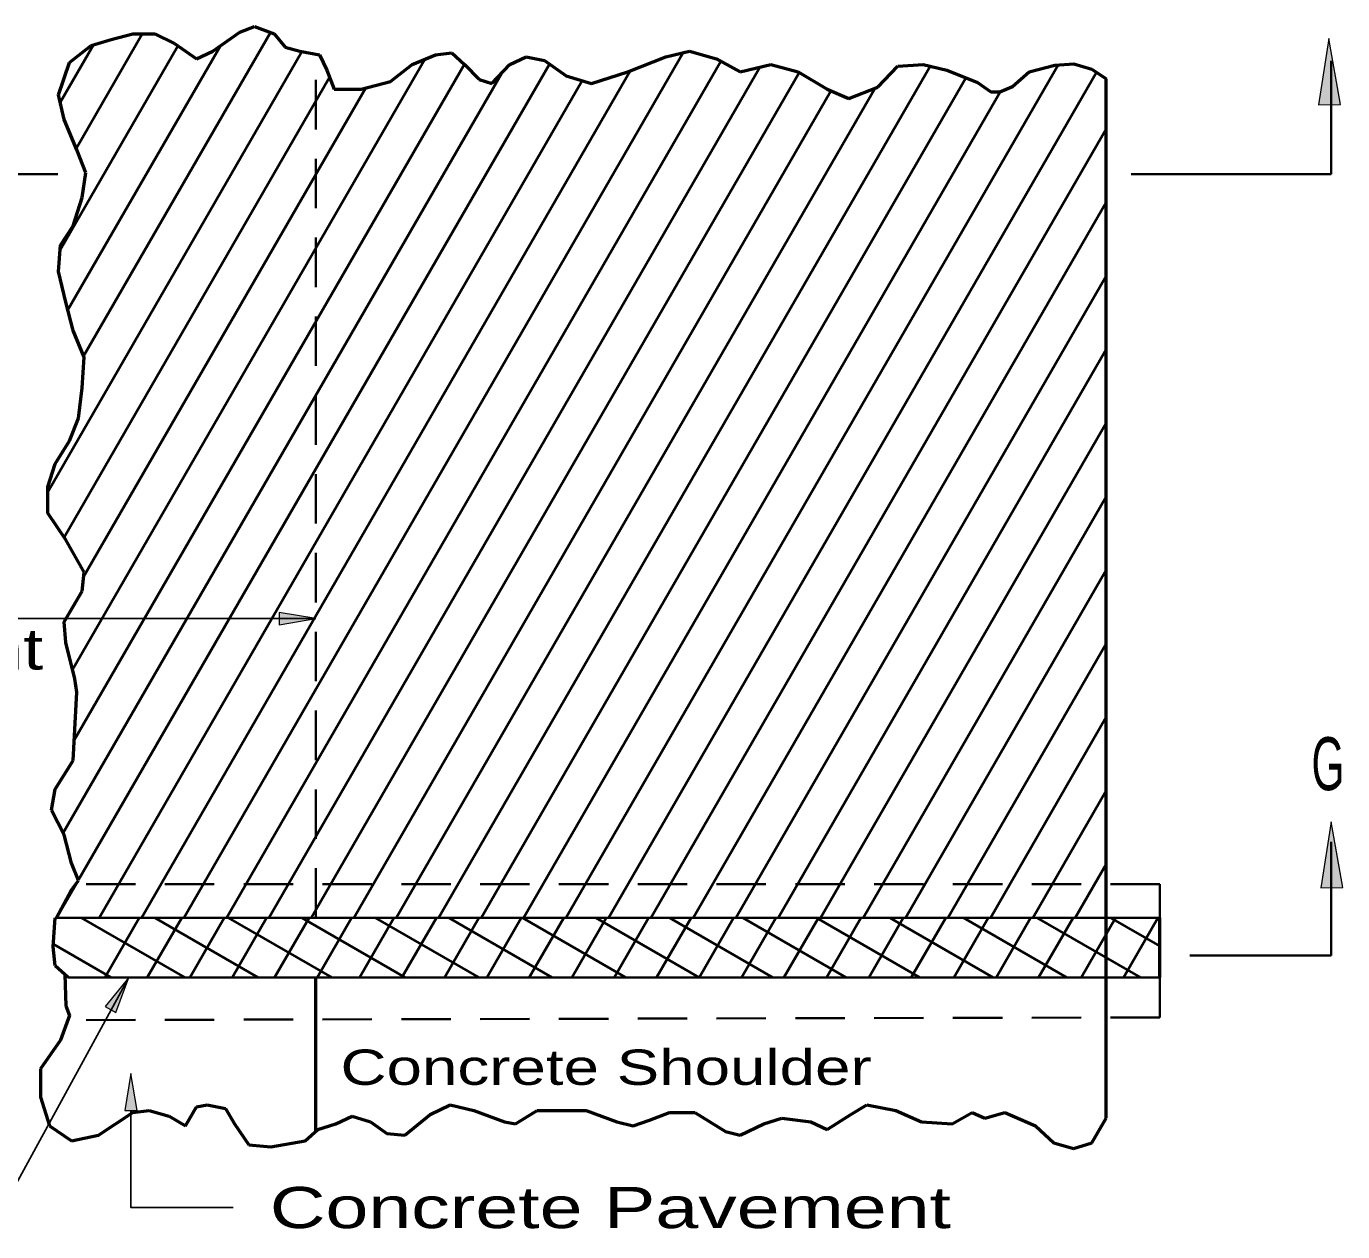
# Model space of a CAD drawing. Extents: x 14 to 49.3, y 28 to 50.
# Drawn here: x 25.568 to 30.044, y 32.796 to 36.894 of the extents above; entities that cross this region are included whole.
import ezdxf

# ---------------------------------------------------------------- set-up
doc = ezdxf.new("R2010")
doc.units = 0
doc.header["$LTSCALE"] = 0.056
doc.linetypes.add('MEDIUM_DASHED', pattern=[4.5, 3, -1.5])
for name, color, linetype, lineweight in [('1', 7, 'Continuous', 35), ('2', 7, 'MEDIUM_DASHED', 35), ('3', 7, 'Continuous', 13), ('5', 7, 'Continuous', 35)]:
    doc.layers.add(name, color=color, linetype=linetype, lineweight=lineweight)

msp = doc.modelspace()

# ---------------------------------------------------------------- hatches: boundary and pattern name
at = {"layer": '3'}
for points in [[(29.96183, 36.62733), (30.03667, 36.628), (29.99783, 36.852), (29.99783, 36.852)], [(29.96183, 36.62733), (30.03667, 36.628), (29.99783, 36.852), (29.99783, 36.852)], [(26.42775, 34.90125), (26.42775, 34.85958), (26.55275, 34.88042), (26.55275, 34.88042)], [(29.96967, 33.96517), (30.0445, 33.96583), (30.00567, 34.18983), (30.00567, 34.18983)], [(25.83633, 33.562), (25.87267, 33.54142), (25.91625, 33.66042), (25.91625, 33.66042)], [(25.90292, 33.20842), (25.94458, 33.20842), (25.92375, 33.33342), (25.92375, 33.33342)]]:
    msp.add_hatch(color=256, dxfattribs=at).paths.add_polyline_path(points)

# ---------------------------------------------------------------- linework, layer by layer
at = {"layer": '1', "lineweight": 53}
for p, q in [((26.29425, 36.87433), (26.3435, 36.89375)), ((26.3435, 36.89375), (26.41133, 36.86792)), ((25.78883, 36.82908), (25.85658, 36.8485)), ((25.85658, 36.8485), (25.93058, 36.86792)), ((25.93058, 36.86792), (26.0045, 36.86792)), ((26.0045, 36.86792), (26.07233, 36.83558)), ((26.20175, 36.80967), (26.29425, 36.87433)), ((26.41133, 36.86792), (26.44833, 36.82267)), ((25.71483, 36.77092), (25.78883, 36.82908)), ((26.07233, 36.83558), (26.14625, 36.78383)), ((26.14625, 36.78383), (26.20175, 36.80967)), ((26.44833, 36.82267), (26.49758, 36.80967)), ((26.49758, 36.80967), (26.56542, 36.79675)), ((26.95992, 36.79675), (27.01533, 36.80325)), ((27.01533, 36.80325), (27.0585, 36.76442)), ((27.74267, 36.79033), (27.82275, 36.80967)), ((27.82275, 36.80967), (27.91525, 36.78383)), ((25.67783, 36.661), (25.71483, 36.77092)), ((26.56542, 36.79675), (26.59008, 36.745)), ((26.80583, 36.70625), (26.87975, 36.76442)), ((26.87975, 36.76442), (26.95992, 36.79675)), ((27.0585, 36.76442), (27.10783, 36.71275)), ((27.15092, 36.69975), (27.21258, 36.76442)), ((27.21258, 36.76442), (27.26808, 36.79033)), ((27.26808, 36.79033), (27.32967, 36.77733)), ((27.32967, 36.77733), (27.40367, 36.72567)), ((27.61325, 36.73858), (27.74267, 36.79033)), ((27.91525, 36.78383), (27.99533, 36.73858)), ((27.99533, 36.73858), (28.10017, 36.76442)), ((28.10017, 36.76442), (28.19258, 36.73858)), ((28.46383, 36.68683), (28.53158, 36.758)), ((28.53158, 36.758), (28.61792, 36.76442)), ((28.61792, 36.76442), (28.698, 36.745)), ((28.97858, 36.73908), (29.0655, 36.76192)), ((29.0655, 36.76192), (29.13075, 36.7665)), ((29.13075, 36.7665), (29.19158, 36.74825)), ((26.59008, 36.745), (26.61475, 36.68042)), ((27.10783, 36.71275), (27.15092, 36.69975)), ((27.40367, 36.72567), (27.48992, 36.69975)), ((27.48992, 36.69975), (27.61325, 36.73858)), ((28.19258, 36.73858), (28.29125, 36.68042)), ((28.698, 36.745), (28.80283, 36.70275)), ((28.92208, 36.68892), (28.97858, 36.73908)), ((29.19158, 36.74825), (29.24042, 36.71558)), ((29.24042, 33.18192), (29.24042, 36.71558)), ((26.61475, 36.68042), (26.70717, 36.68042)), ((26.70717, 36.68042), (26.80583, 36.70625)), ((28.29125, 36.68042), (28.36517, 36.64808)), ((28.36517, 36.64808), (28.46383, 36.68683)), ((28.80283, 36.70275), (28.84817, 36.67067)), ((28.84817, 36.67067), (28.87858, 36.67067)), ((28.87858, 36.67067), (28.92208, 36.68892)), ((25.69633, 36.57692), (25.67783, 36.661)), ((25.7395, 36.47342), (25.69633, 36.57692)), ((25.77033, 36.39583), (25.7395, 36.47342)), ((25.758, 36.312), (25.77033, 36.39583)), ((25.72717, 36.215), (25.758, 36.312)), ((25.684, 36.15033), (25.72717, 36.215)), ((25.67783, 36.05975), (25.684, 36.15033)), ((25.7025, 35.95633), (25.67783, 36.05975)), ((25.72717, 35.85933), (25.7025, 35.95633)), ((25.76417, 35.76875), (25.72717, 35.85933)), ((25.758, 35.66525), (25.76417, 35.76875)), ((25.74567, 35.56183), (25.758, 35.66525)), ((25.71483, 35.48425), (25.74567, 35.56183)), ((25.6655, 35.40658), (25.71483, 35.48425)), ((25.64083, 35.32875), (25.6655, 35.40658)), ((25.64083, 35.23825), (25.64083, 35.32875)), ((25.7025, 35.14767), (25.64083, 35.23825)), ((25.76417, 35.03775), (25.7025, 35.14767)), ((25.758, 34.97308), (25.76417, 35.03775)), ((25.69633, 34.86967), (25.758, 34.97308)), ((25.7025, 34.7985), (25.69633, 34.86967)), ((25.73333, 34.67567), (25.7025, 34.7985)), ((25.7395, 34.63042), (25.73333, 34.67567)), ((25.72717, 34.39758), (25.7395, 34.63042)), ((25.6655, 34.30058), (25.72717, 34.39758)), ((25.65317, 34.2295), (25.6655, 34.30058)), ((25.69633, 34.14542), (25.65317, 34.2295)), ((25.721, 34.04842), (25.69633, 34.14542)), ((25.74567, 33.99017), (25.721, 34.04842)), ((25.721, 33.95783), (25.74567, 33.99017)), ((25.67017, 33.86342), (25.721, 33.95783)), ((25.65933, 33.76392), (25.66617, 33.86342)), ((29.42325, 33.66042), (29.42325, 33.86342)), ((25.6655, 33.69925), (25.65933, 33.76392)), ((25.71017, 33.66042), (25.6655, 33.69925)), ((25.69925, 33.66992), (25.7025, 33.56342)), ((26.55083, 33.66042), (26.55083, 33.13558)), ((25.71483, 33.53108), (25.684, 33.447)), ((25.7025, 33.56342), (25.71483, 33.53108)), ((25.684, 33.447), (25.61625, 33.35)), ((25.61625, 33.35), (25.61625, 33.253)), ((25.61625, 33.253), (25.647, 33.15608)), ((26.10933, 33.15608), (26.14625, 33.22067)), ((26.14625, 33.22067), (26.18325, 33.22717)), ((26.18325, 33.22717), (26.24492, 33.21425)), ((26.94142, 33.19483), (27.00917, 33.22717)), ((27.00917, 33.22717), (27.08933, 33.20775)), ((28.37133, 33.19483), (28.42683, 33.22717)), ((28.42683, 33.22717), (28.52542, 33.20775)), ((25.81342, 33.12375), (25.93058, 33.20133)), ((25.93058, 33.20133), (25.986, 33.20775)), ((25.986, 33.20775), (26.05383, 33.18833)), ((26.05383, 33.18833), (26.10933, 33.15608)), ((26.24492, 33.21425), (26.27575, 33.1625)), ((26.62092, 33.1625), (26.67633, 33.18833)), ((26.67633, 33.18833), (26.738, 33.169)), ((26.85508, 33.12375), (26.94142, 33.19483)), ((27.08933, 33.20775), (27.19408, 33.169)), ((27.23108, 33.1625), (27.30508, 33.20775)), ((27.30508, 33.20775), (27.38517, 33.20775)), ((27.38517, 33.20775), (27.4715, 33.20775)), ((27.4715, 33.20775), (27.57625, 33.169)), ((27.63175, 33.15608), (27.68717, 33.17542)), ((27.68717, 33.17542), (27.755, 33.20133)), ((27.755, 33.20133), (27.84125, 33.20133)), ((27.84125, 33.20133), (27.94608, 33.13667)), ((28.0755, 33.1625), (28.13717, 33.18192)), ((28.13717, 33.18192), (28.23575, 33.169)), ((28.29125, 33.14308), (28.37133, 33.19483)), ((28.52542, 33.20775), (28.61175, 33.169)), ((28.7165, 33.1625), (28.78433, 33.20133)), ((28.78433, 33.20133), (28.82742, 33.18192)), ((28.82742, 33.18192), (28.89525, 33.20133)), ((28.89525, 33.20133), (29, 33.15608)), ((29.19108, 33.09783), (29.24042, 33.18192)), ((25.647, 33.15608), (25.721, 33.10433)), ((26.27575, 33.1625), (26.325, 33.09142)), ((26.51608, 33.10433), (26.55925, 33.14308)), ((26.55925, 33.14308), (26.62092, 33.1625)), ((26.738, 33.169), (26.7935, 33.13017)), ((26.7935, 33.13017), (26.85508, 33.12375)), ((27.19408, 33.169), (27.23108, 33.1625)), ((27.57625, 33.169), (27.63175, 33.15608)), ((27.94608, 33.13667), (27.99533, 33.12375)), ((27.99533, 33.12375), (28.0755, 33.1625)), ((28.23575, 33.169), (28.29125, 33.14308)), ((28.61175, 33.169), (28.7165, 33.1625)), ((29, 33.15608), (29.06167, 33.09783)), ((25.721, 33.10433), (25.81342, 33.12375)), ((26.325, 33.09142), (26.399, 33.08492)), ((26.399, 33.08492), (26.51608, 33.10433)), ((29.06167, 33.09783), (29.1295, 33.07842)), ((29.1295, 33.07842), (29.19108, 33.09783))]:
    msp.add_line(p, q, dxfattribs=at)
at = {"layer": '1', "lineweight": 40}
for p, q in [((25.73742, 36.4785), (25.96225, 36.86792)), ((25.76267, 35.77225), (26.39817, 36.87292)), ((25.64083, 35.31125), (26.50517, 36.80825)), ((25.68292, 36.13408), (26.08342, 36.82783)), ((25.6835, 36.63517), (25.79683, 36.83142)), ((25.70925, 35.92975), (26.22783, 36.82792)), ((26.104, 33.86342), (27.80217, 36.80475)), ((25.72533, 34.70758), (26.92292, 36.78183)), ((25.73083, 34.46708), (27.05767, 36.76517)), ((25.745, 33.99167), (27.34658, 36.76558)), ((26.24833, 33.86342), (27.92975, 36.77567)), ((26.39267, 33.86342), (28.06217, 36.75508)), ((26.97, 33.86342), (28.64158, 36.75867)), ((27.403, 33.86342), (29.07692, 36.76267)), ((25.69308, 34.15175), (27.18458, 36.73508)), ((25.69617, 35.157), (26.59917, 36.72108)), ((25.81533, 33.86342), (27.45833, 36.70925)), ((25.95967, 33.86342), (27.62158, 36.74192)), ((26.537, 33.86342), (28.19583, 36.73667)), ((27.11433, 33.86342), (28.76292, 36.71883)), ((27.54733, 33.86342), (29.207, 36.73792)), ((25.76267, 35.02225), (26.72225, 36.68433)), ((26.68133, 33.86342), (28.30442, 36.67458)), ((26.82567, 33.86342), (28.45342, 36.68275)), ((27.25867, 33.86342), (28.87975, 36.67117)), ((27.69167, 33.86342), (29.24042, 36.54583)), ((27.83608, 33.86342), (29.24042, 36.29583)), ((27.98042, 33.86342), (29.24042, 36.04583)), ((28.12475, 33.86342), (29.24042, 35.79583)), ((28.26908, 33.86342), (29.24042, 35.54583)), ((28.41342, 33.86342), (29.24042, 35.29583)), ((28.55775, 33.86342), (29.24042, 35.04583)), ((28.70208, 33.86342), (29.24042, 34.79583)), ((28.84642, 33.86342), (29.24042, 34.54583)), ((28.99075, 33.86342), (29.24042, 34.29583)), ((29.13508, 33.86342), (29.24042, 34.04583)), ((25.671, 33.86342), (25.73958, 33.98225)), ((25.75475, 33.86342), (26.10642, 33.66042)), ((25.83492, 33.66042), (25.95208, 33.86342)), ((25.97925, 33.66042), (26.0965, 33.86342)), ((26.00475, 33.86342), (26.35642, 33.66042)), ((26.12358, 33.66042), (26.24083, 33.86342)), ((26.25475, 33.86342), (26.60642, 33.66042)), ((26.26792, 33.66042), (26.38517, 33.86342)), ((26.41225, 33.66042), (26.5295, 33.86342)), ((26.50475, 33.86342), (26.85642, 33.66042)), ((26.55658, 33.66042), (26.67383, 33.86342)), ((26.70092, 33.66042), (26.81817, 33.86342)), ((26.75475, 33.86342), (27.10642, 33.66042)), ((26.84525, 33.66042), (26.9625, 33.86342)), ((26.98958, 33.66042), (27.10683, 33.86342)), ((27.00475, 33.86342), (27.35642, 33.66042)), ((27.13392, 33.66042), (27.25117, 33.86342)), ((27.25475, 33.86342), (27.60642, 33.66042)), ((27.27825, 33.66042), (27.3955, 33.86342)), ((27.42258, 33.66042), (27.53983, 33.86342)), ((27.50475, 33.86342), (27.85642, 33.66042)), ((27.56692, 33.66042), (27.68417, 33.86342)), ((27.71125, 33.66042), (27.8285, 33.86342)), ((27.75475, 33.86342), (28.10642, 33.66042)), ((27.85567, 33.66042), (27.97283, 33.86342)), ((28, 33.66042), (28.11717, 33.86342)), ((28.00475, 33.86342), (28.35642, 33.66042)), ((28.14433, 33.66042), (28.2615, 33.86342)), ((28.25475, 33.86342), (28.60642, 33.66042)), ((28.28867, 33.66042), (28.40583, 33.86342)), ((28.433, 33.66042), (28.55017, 33.86342)), ((28.50475, 33.86342), (28.85642, 33.66042)), ((28.57733, 33.66042), (28.6945, 33.86342)), ((28.72167, 33.66042), (28.83883, 33.86342)), ((28.75475, 33.86342), (29.10642, 33.66042)), ((28.866, 33.66042), (28.98325, 33.86342)), ((29.00475, 33.86342), (29.35642, 33.66042)), ((29.01033, 33.66042), (29.12758, 33.86342)), ((29.15467, 33.66042), (29.27192, 33.86342)), ((29.25475, 33.86342), (29.42325, 33.76617)), ((29.299, 33.66042), (29.41625, 33.86342)), ((25.66, 33.77383), (25.85642, 33.66042))]:
    msp.add_line(p, q, dxfattribs=at)
at = {"layer": '1'}
for p, q in [((28.80283, 33.86342), (25.66617, 33.86342)), ((29.42325, 33.86342), (28.80283, 33.86342)), ((25.71017, 33.66042), (29.42325, 33.66042))]:
    msp.add_line(p, q, dxfattribs=at)
at = {"layer": '2'}
for p, q in [((26.55275, 33.86342), (26.55275, 36.79917)), ((29.42325, 33.97725), (25.77033, 33.97725)), ((29.42325, 33.97725), (29.42325, 33.86342)), ((29.42325, 33.66042), (29.42325, 33.52467)), ((29.42325, 33.52467), (25.70908, 33.51542))]:
    msp.add_line(p, q, dxfattribs=at)
at = {"layer": '3', "lineweight": 25}
msp.add_line((26.55275, 34.88042), (24.45583, 34.88042), dxfattribs=at)
at = {"layer": '3'}
for points in [[(29.96183, 36.62733), (30.03667, 36.628), (29.99783, 36.852), (29.99783, 36.852)], [(29.96183, 36.62733), (30.03667, 36.628), (29.99783, 36.852), (29.99783, 36.852)], [(26.42775, 34.90125), (26.42775, 34.85958), (26.55275, 34.88042), (26.55275, 34.88042)], [(29.96967, 33.96517), (30.0445, 33.96583), (30.00567, 34.18983), (30.00567, 34.18983)], [(25.83633, 33.562), (25.87267, 33.54142), (25.91625, 33.66042), (25.91625, 33.66042)], [(25.90292, 33.20842), (25.94458, 33.20842), (25.92375, 33.33342), (25.92375, 33.33342)]]:
    msp.add_lwpolyline(points, close=True, dxfattribs=at)
at = {"layer": '3', "lineweight": 25}
for points in [[(25.91625, 33.66042), (25.44375, 32.79608), (25.05367, 32.79608)], [(25.92375, 33.20842), (25.92375, 32.87808), (26.271, 32.87808)]]:
    msp.add_lwpolyline(points, dxfattribs=at)
at = {"layer": '5'}
for p, q in [((30.00567, 36.777), (30.00567, 36.39083)), ((24.87575, 36.39083), (25.67525, 36.39083)), ((29.32483, 36.39083), (30.00567, 36.39083)), ((30.00567, 34.121), (30.00567, 33.73483)), ((29.52517, 33.73483), (30.00567, 33.73483))]:
    msp.add_line(p, q, dxfattribs=at)

# ---------------------------------------------------------------- texts
at = {"layer": '3'}
for s, height, width, p in [('Pavement', 0.14, 1.3, (24.52908, 34.70692)), ('Concrete Shoulder', 0.12, 1.35, (26.63642, 33.29517)), ('Concrete Pavement', 0.14, 1.4, (26.396, 32.80808))]:
    msp.add_text(s, height=height, dxfattribs=dict(at, width=width)).set_placement(p)
at = {"layer": '5', "width": 0.6}
msp.add_text('G', height=0.18, dxfattribs=at).set_placement((29.9385, 34.297))

doc.saveas('drawing.dxf')
